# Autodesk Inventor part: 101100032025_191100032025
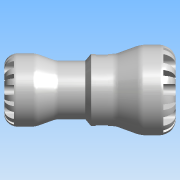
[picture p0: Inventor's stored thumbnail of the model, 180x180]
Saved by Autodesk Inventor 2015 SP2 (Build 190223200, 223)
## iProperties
Created: 2016-12
Part Number: 101100032025_191100032025
Material: PVC-Piping
Description: PLASSON REDUCING COUPLING 32X25 SERIES 1
Document SubType Name: Modeling
Designer: KIM
Mass: 113.204 g
Surface Area: 237.851 cm^2
Volume: 80.8599 cm^3
Density: 1.4 g/cm^3
Appearance: Smooth - White
Author: KIM
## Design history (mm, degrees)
derived "1011.ipt"
feature "Solid1::1011.ipt"
tag "TaggingFeature1"
body "Solid1"
other parameters: "d2" = 22.68, "d3" = 32, "d4" = 58, "d5" = 38.4, "d6" = 54, "d7" = 2.66667, "d8" = 47, "d9" = 25, "d10" = 31.25, "d11" = 20.16, "d12" = 48, "d13" = 2.08333, "d14" = 46.4, "d15" = 37.6, "d16" = 20 deg, "d17" = 20 deg, "d18" = 130 deg, "d22" = 7.84, "d25" = 7.84, "d26" = 0, "d28" = 360 deg, "d30" = 8 deg, "d31" = 0.64, "d32" = 8 deg, "d33" = 0.64, "d35" = 0, "d37" = 360 deg, "d39" = 6.3, "d42" = 6.3, "d43" = 0, "d45" = 360 deg, "d47" = 0.5, "d48" = 8 deg, "d49" = 8 deg, "d50" = 0.5, "d52" = 0, "d54" = 360 deg, "d56" = 9.4, "d57" = 11.6, "d58" = 0.5, "d60" = 6.96, "d61" = 8, "d62" = 12.96, "d63" = 0, "d66" = 0, "d68" = 360 deg, "d75" = 6.70702, "d77" = 45.24, "d78" = 0.58, "d_" = 32, "d1" = 25, "E_" = 58, "l_" = 54, "E1" = 47, "l1" = 48, "Plasson" = 1, "d20" = 7.875, "d21" = 9.8, "d23" = 58, "d24" = 38.4, "d40" = 47, "d41" = 31.25, "d59" = 13.41405
